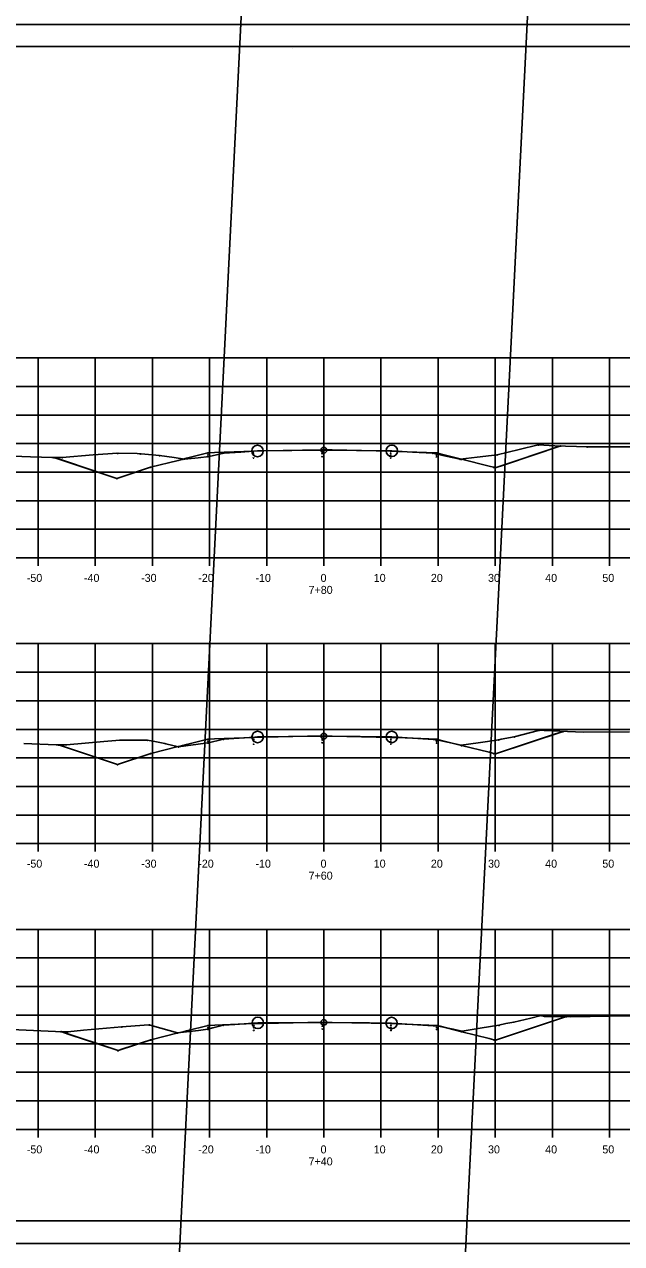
# Model space of a CAD drawing. Extents: x 1300404 to 1323571, y 234004 to 252077.
# Drawn here: x 1315664.9 to 1315769.4, y 242555.1 to 242768.5 of the extents above; entities that cross this region are included whole.
import ezdxf

# ---------------------------------------------------------------- set-up
doc = ezdxf.new("R2010")
doc.units = 0
for name, color, linetype in [('Default', 7, 'Continuous'), ('R_Axis', 7, 'Continuous'), ('R_Axis Annot', 7, 'Continuous'), ('R_Border', 7, 'Continuous'), ('R_Draft', 7, 'Continuous'), ('R_Exist Surface', 7, 'Continuous'), ('R_Fin Surface', 7, 'Continuous'), ('R_Floodway', 7, 'Continuous'), ('R_Grid', 7, 'Continuous'), ('R_No Plot', 7, 'Continuous')]:
    doc.layers.add(name, color=color, linetype=linetype)

msp = doc.modelspace()

# ---------------------------------------------------------------- linework, layer by layer
at = {"layer": 'Default'}
for p, q in [((1315559.28, 242764.58), (1315875.46, 242764.58)), ((1315875.46, 242559.12), (1315559.28, 242559.12))]:
    msp.add_line(p, q, dxfattribs=at)
at = {"layer": 'R_Axis'}
for p, q in [((1315577.28, 242675.12), (1315857.28, 242675.12)), ((1315667.28, 242673.72), (1315667.28, 242675.12)), ((1315677.28, 242673.72), (1315677.28, 242675.12)), ((1315687.28, 242673.72), (1315687.28, 242675.12)), ((1315697.28, 242673.72), (1315697.28, 242675.12)), ((1315707.28, 242673.72), (1315707.28, 242675.12)), ((1315717.28, 242673.72), (1315717.28, 242675.12)), ((1315727.28, 242673.72), (1315727.28, 242675.12)), ((1315737.28, 242673.72), (1315737.28, 242675.12)), ((1315747.28, 242673.72), (1315747.28, 242675.12)), ((1315757.28, 242673.72), (1315757.28, 242675.12)), ((1315767.28, 242673.72), (1315767.28, 242675.12)), ((1315577.28, 242625.12), (1315857.28, 242625.12)), ((1315667.28, 242623.72), (1315667.28, 242625.12)), ((1315677.28, 242623.72), (1315677.28, 242625.12)), ((1315687.28, 242623.72), (1315687.28, 242625.12)), ((1315697.28, 242623.72), (1315697.28, 242625.12)), ((1315707.28, 242623.72), (1315707.28, 242625.12)), ((1315717.28, 242623.72), (1315717.28, 242625.12)), ((1315727.28, 242623.72), (1315727.28, 242625.12)), ((1315737.28, 242623.72), (1315737.28, 242625.12)), ((1315747.28, 242623.72), (1315747.28, 242625.12)), ((1315757.28, 242623.72), (1315757.28, 242625.12)), ((1315767.28, 242623.72), (1315767.28, 242625.12)), ((1315577.28, 242575.12), (1315857.28, 242575.12)), ((1315667.28, 242573.72), (1315667.28, 242575.12)), ((1315677.28, 242573.72), (1315677.28, 242575.12)), ((1315687.28, 242573.72), (1315687.28, 242575.12)), ((1315697.28, 242573.72), (1315697.28, 242575.12)), ((1315707.28, 242573.72), (1315707.28, 242575.12)), ((1315717.28, 242573.72), (1315717.28, 242575.12)), ((1315727.28, 242573.72), (1315727.28, 242575.12)), ((1315737.28, 242573.72), (1315737.28, 242575.12)), ((1315747.28, 242573.72), (1315747.28, 242575.12)), ((1315757.28, 242573.72), (1315757.28, 242575.12)), ((1315767.28, 242573.72), (1315767.28, 242575.12))]:
    msp.add_line(p, q, dxfattribs=at)
at = {"layer": 'R_Border'}
msp.add_line((1315711.8, 242764.32), (1315711.8, 242764.32), dxfattribs=at)
msp.add_line((1315711.8, 242764.32), (1315711.8, 242764.32), dxfattribs=at)
at = {"layer": 'R_Draft'}
for points in [[(1315681.19, 242693.48), (1315681.24, 242693.38), (1315681.14, 242693.38)], [(1315685.16, 242693.4), (1315685.21, 242693.3), (1315685.11, 242693.3)], [(1315696.98, 242693.54), (1315697.03, 242693.44), (1315696.93, 242693.44)], [(1315699.78, 242693.52), (1315699.83, 242693.42), (1315699.73, 242693.42)], [(1315704.98, 242693.86), (1315705.03, 242693.76), (1315704.93, 242693.76)], [(1315704.98, 242693.53), (1315705.03, 242693.43), (1315704.93, 242693.43)], [(1315716.98, 242694.1), (1315717.03, 242694), (1315716.93, 242694)], [(1315716.98, 242693.77), (1315717.03, 242693.67), (1315716.93, 242693.67)], [(1315716.98, 242693.44), (1315717.03, 242693.34), (1315716.93, 242693.34)], [(1315728.98, 242693.86), (1315729.03, 242693.76), (1315728.93, 242693.76)], [(1315728.98, 242693.53), (1315729.03, 242693.43), (1315728.93, 242693.43)], [(1315736.36, 242693.48), (1315736.41, 242693.38), (1315736.31, 242693.38)], [(1315736.98, 242693.54), (1315737.03, 242693.44), (1315736.93, 242693.44)], [(1315754.81, 242694.93), (1315754.86, 242694.83), (1315754.76, 242694.83)], [(1315758.72, 242694.76), (1315758.77, 242694.66), (1315758.67, 242694.66)], [(1315758.72, 242694.76), (1315758.77, 242694.66), (1315758.67, 242694.66)], [(1315763.34, 242694.6), (1315763.39, 242694.5), (1315763.29, 242694.5)], [(1315670.04, 242692.75), (1315670.09, 242692.65), (1315669.99, 242692.65)], [(1315670.04, 242692.75), (1315670.09, 242692.65), (1315669.99, 242692.65)], [(1315671.52, 242692.75), (1315671.57, 242692.65), (1315671.47, 242692.65)], [(1315688.51, 242693.09), (1315688.56, 242692.99), (1315688.46, 242692.99)], [(1315692.61, 242692.45), (1315692.66, 242692.35), (1315692.56, 242692.35)], [(1315692.88, 242692.47), (1315692.93, 242692.37), (1315692.83, 242692.37)], [(1315696.98, 242693.21), (1315697.03, 242693.11), (1315696.93, 242693.11)], [(1315696.98, 242692.88), (1315697.03, 242692.78), (1315696.93, 242692.78)], [(1315697.23, 242692.89), (1315697.28, 242692.79), (1315697.18, 242692.79)], [(1315704.98, 242693.19), (1315705.03, 242693.09), (1315704.93, 242693.09)], [(1315704.98, 242692.69), (1315705.03, 242692.59), (1315704.93, 242692.59)], [(1315716.98, 242692.93), (1315717.03, 242692.83), (1315716.93, 242692.83)], [(1315728.98, 242693.2), (1315729.03, 242693.1), (1315728.93, 242693.1)], [(1315728.98, 242692.69), (1315729.03, 242692.59), (1315728.93, 242692.59)], [(1315736.98, 242693.21), (1315737.03, 242693.11), (1315736.93, 242693.11)], [(1315736.98, 242692.88), (1315737.03, 242692.78), (1315736.93, 242692.78)], [(1315741.13, 242692.42), (1315741.18, 242692.32), (1315741.08, 242692.32)], [(1315741.36, 242692.45), (1315741.41, 242692.35), (1315741.31, 242692.35)], [(1315747.59, 242693.22), (1315747.64, 242693.12), (1315747.54, 242693.12)], [(1315681.08, 242689.07), (1315681.13, 242688.97), (1315681.03, 242688.97)], [(1315686.98, 242691.04), (1315687.03, 242690.94), (1315686.93, 242690.94)], [(1315746.98, 242691.04), (1315747.03, 242690.94), (1315746.93, 242690.94)], [(1315747.27, 242690.95), (1315747.32, 242690.85), (1315747.22, 242690.85)], [(1315755.05, 242645.02), (1315755.1, 242644.92), (1315755, 242644.92)], [(1315759.15, 242644.81), (1315759.2, 242644.71), (1315759.1, 242644.71)], [(1315759.15, 242644.81), (1315759.2, 242644.71), (1315759.1, 242644.71)], [(1315670.85, 242642.46), (1315670.9, 242642.36), (1315670.8, 242642.36)], [(1315670.85, 242642.46), (1315670.9, 242642.36), (1315670.8, 242642.36)], [(1315672.24, 242642.49), (1315672.29, 242642.39), (1315672.19, 242642.39)], [(1315681.58, 242643.3), (1315681.63, 242643.2), (1315681.53, 242643.2)], [(1315686.4, 242643.29), (1315686.45, 242643.19), (1315686.35, 242643.19)], [(1315692.63, 242642.36), (1315692.68, 242642.26), (1315692.58, 242642.26)], [(1315697, 242643.45), (1315697.05, 242643.35), (1315696.95, 242643.35)], [(1315697, 242643.12), (1315697.05, 242643.02), (1315696.95, 242643.02)], [(1315697, 242642.79), (1315697.05, 242642.69), (1315696.95, 242642.69)], [(1315697.11, 242642.8), (1315697.16, 242642.7), (1315697.06, 242642.7)], [(1315699.74, 242643.47), (1315699.79, 242643.37), (1315699.69, 242643.37)], [(1315705, 242643.77), (1315705.05, 242643.67), (1315704.95, 242643.67)], [(1315705, 242643.44), (1315705.05, 242643.34), (1315704.95, 242643.34)], [(1315705, 242643.11), (1315705.05, 242643.01), (1315704.95, 242643.01)], [(1315705, 242642.61), (1315705.05, 242642.51), (1315704.95, 242642.51)], [(1315717, 242644.01), (1315717.05, 242643.91), (1315716.95, 242643.91)], [(1315717, 242643.68), (1315717.05, 242643.58), (1315716.95, 242643.58)], [(1315717, 242643.35), (1315717.05, 242643.25), (1315716.95, 242643.25)], [(1315717, 242642.85), (1315717.05, 242642.75), (1315716.95, 242642.75)], [(1315729, 242643.77), (1315729.05, 242643.67), (1315728.95, 242643.67)], [(1315729, 242643.44), (1315729.05, 242643.34), (1315728.95, 242643.34)], [(1315729, 242643.11), (1315729.05, 242643.01), (1315728.95, 242643.01)], [(1315729, 242642.61), (1315729.05, 242642.51), (1315728.95, 242642.51)], [(1315736.85, 242643.36), (1315736.9, 242643.26), (1315736.8, 242643.26)], [(1315737, 242643.45), (1315737.05, 242643.35), (1315736.95, 242643.35)], [(1315737, 242643.12), (1315737.05, 242643.02), (1315736.95, 242643.02)], [(1315737, 242642.79), (1315737.05, 242642.69), (1315736.95, 242642.69)], [(1315741.32, 242642.4), (1315741.37, 242642.3), (1315741.27, 242642.3)], [(1315741.38, 242642.36), (1315741.43, 242642.26), (1315741.33, 242642.26)], [(1315747.89, 242643.35), (1315747.94, 242643.25), (1315747.84, 242643.25)], [(1315750.61, 242643.88), (1315750.66, 242643.78), (1315750.56, 242643.78)], [(1315687, 242640.95), (1315687.05, 242640.85), (1315686.95, 242640.85)], [(1315691.85, 242642.09), (1315691.9, 242641.99), (1315691.8, 242641.99)], [(1315747, 242640.95), (1315747.05, 242640.85), (1315746.95, 242640.85)], [(1315747.29, 242640.86), (1315747.34, 242640.76), (1315747.24, 242640.76)], [(1315681.18, 242639.01), (1315681.23, 242638.91), (1315681.13, 242638.91)], [(1315681.95, 242593.13), (1315682, 242593.03), (1315681.9, 242593.03)], [(1315686.72, 242593.45), (1315686.77, 242593.35), (1315686.67, 242593.35)], [(1315697.02, 242593.36), (1315697.07, 242593.26), (1315696.97, 242593.26)], [(1315699.7, 242593.41), (1315699.75, 242593.31), (1315699.65, 242593.31)], [(1315705.02, 242593.68), (1315705.07, 242593.58), (1315704.97, 242593.58)], [(1315705.02, 242593.35), (1315705.07, 242593.25), (1315704.97, 242593.25)], [(1315717.02, 242593.92), (1315717.07, 242593.82), (1315716.97, 242593.82)], [(1315717.02, 242593.59), (1315717.07, 242593.49), (1315716.97, 242593.49)], [(1315717.02, 242593.26), (1315717.07, 242593.16), (1315716.97, 242593.16)], [(1315729.02, 242593.68), (1315729.07, 242593.58), (1315728.97, 242593.58)], [(1315729.02, 242593.35), (1315729.07, 242593.25), (1315728.97, 242593.25)], [(1315737.02, 242593.36), (1315737.07, 242593.26), (1315736.97, 242593.26)], [(1315737.33, 242593.25), (1315737.38, 242593.15), (1315737.28, 242593.15)], [(1315747.91, 242593.38), (1315747.96, 242593.28), (1315747.86, 242593.28)], [(1315750.51, 242593.96), (1315750.56, 242593.86), (1315750.46, 242593.86)], [(1315755.28, 242595.11), (1315755.33, 242595.01), (1315755.23, 242595.01)], [(1315759.74, 242594.91), (1315759.79, 242594.81), (1315759.69, 242594.81)], [(1315759.74, 242594.91), (1315759.79, 242594.81), (1315759.69, 242594.81)], [(1315671.26, 242592.29), (1315671.31, 242592.19), (1315671.21, 242592.19)], [(1315671.26, 242592.29), (1315671.31, 242592.19), (1315671.21, 242592.19)], [(1315672.47, 242592.26), (1315672.52, 242592.16), (1315672.42, 242592.16)], [(1315691.69, 242592.07), (1315691.74, 242591.97), (1315691.64, 242591.97)], [(1315692.64, 242592.27), (1315692.69, 242592.17), (1315692.59, 242592.17)], [(1315696.99, 242592.72), (1315697.04, 242592.62), (1315696.94, 242592.62)], [(1315697.02, 242593.03), (1315697.07, 242592.93), (1315696.97, 242592.93)], [(1315697.02, 242592.7), (1315697.07, 242592.6), (1315696.97, 242592.6)], [(1315705.02, 242593.02), (1315705.07, 242592.92), (1315704.97, 242592.92)], [(1315705.02, 242592.52), (1315705.07, 242592.42), (1315704.97, 242592.42)], [(1315717.02, 242592.76), (1315717.07, 242592.66), (1315716.97, 242592.66)], [(1315729.02, 242593.02), (1315729.07, 242592.92), (1315728.97, 242592.92)], [(1315729.02, 242592.52), (1315729.07, 242592.42), (1315728.97, 242592.42)], [(1315737.02, 242593.03), (1315737.07, 242592.93), (1315736.97, 242592.93)], [(1315737.02, 242592.7), (1315737.07, 242592.6), (1315736.97, 242592.6)], [(1315741.4, 242592.27), (1315741.45, 242592.17), (1315741.35, 242592.17)], [(1315741.5, 242592.38), (1315741.55, 242592.28), (1315741.45, 242592.28)], [(1315681.28, 242588.95), (1315681.33, 242588.85), (1315681.23, 242588.85)], [(1315687.02, 242590.86), (1315687.07, 242590.76), (1315686.97, 242590.76)], [(1315747.02, 242590.86), (1315747.07, 242590.76), (1315746.97, 242590.76)], [(1315747.3, 242590.77), (1315747.35, 242590.67), (1315747.25, 242590.67)]]:
    msp.add_lwpolyline(points, close=True, dxfattribs=at)
at = {"layer": 'R_Exist Surface'}
for points in [[(1315658.35, 242693.07), (1315665.95, 242692.82), (1315667.9, 242692.72), (1315669.7, 242692.69), (1315671.52, 242692.7), (1315676.93, 242693.14), (1315681.19, 242693.43), (1315684.6, 242693.38), (1315685.16, 242693.35), (1315685.34, 242693.34), (1315688.51, 242693.04), (1315691.08, 242692.68), (1315692.88, 242692.42), (1315695.28, 242692.65), (1315697.23, 242692.84), (1315698.51, 242693.16), (1315699.78, 242693.47), (1315702.75, 242693.65), (1315705.67, 242693.83), (1315711.7, 242693.9), (1315717.3, 242693.96), (1315723.01, 242693.9), (1315729.18, 242693.85), (1315732.82, 242693.64), (1315736.36, 242693.43), (1315738.61, 242692.93), (1315741.13, 242692.37), (1315744.08, 242692.76), (1315747.59, 242693.17), (1315751.47, 242694.1), (1315754.81, 242694.88), (1315757.71, 242694.72), (1315763.34, 242694.55), (1315772.4, 242694.53)], [(1315664.78, 242642.62), (1315670.46, 242642.39), (1315672.24, 242642.44), (1315678.76, 242643.01), (1315681.58, 242643.25), (1315682.32, 242643.21), (1315686.4, 242643.24), (1315687.98, 242642.96), (1315689.44, 242642.64), (1315689.63, 242642.59), (1315691.85, 242642.04), (1315696.59, 242642.68), (1315697.11, 242642.75), (1315699.51, 242643.36), (1315699.74, 242643.42), (1315705.23, 242643.76), (1315705.7, 242643.79), (1315716.45, 242643.9), (1315717.28, 242643.91), (1315718.15, 242643.9), (1315729.16, 242643.79), (1315736.42, 242643.34), (1315736.85, 242643.31), (1315737.06, 242643.27), (1315741.32, 242642.35), (1315744.26, 242642.78), (1315747.89, 242643.3), (1315748.28, 242643.39), (1315748.32, 242643.39), (1315750.61, 242643.83), (1315754.84, 242644.92), (1315755.05, 242644.97), (1315755.81, 242644.92), (1315762.65, 242644.63), (1315770.79, 242644.69)], [(1315657.46, 242592.81), (1315670.33, 242592.26), (1315671.96, 242592.2), (1315672.47, 242592.21), (1315675.25, 242592.46), (1315681.95, 242593.08), (1315685.84, 242593.35), (1315686.72, 242593.4), (1315687.28, 242593.23), (1315691.69, 242592.02), (1315695.33, 242592.42), (1315696.99, 242592.67), (1315697.83, 242592.88), (1315699.7, 242593.36), (1315701.69, 242593.49), (1315705.74, 242593.75), (1315709.58, 242593.79), (1315717.27, 242593.85), (1315725.28, 242593.77), (1315729.14, 242593.73), (1315731.82, 242593.56), (1315737.33, 242593.2), (1315739.92, 242592.67), (1315741.5, 242592.33), (1315744.61, 242592.83), (1315747.91, 242593.33), (1315749.13, 242593.66), (1315750.51, 242593.91), (1315753.49, 242594.59), (1315755.28, 242595.06), (1315755.87, 242594.85), (1315758.86, 242594.86), (1315760.36, 242594.84), (1315770.81, 242594.98)]]:
    msp.add_lwpolyline(points, dxfattribs=at)
at = {"layer": 'R_Fin Surface'}
for points in [[(1315670.04, 242692.7), (1315671.73, 242692.14), (1315681.08, 242689.02), (1315681.95, 242689.31), (1315686.98, 242690.99), (1315691.78, 242692.19), (1315692.61, 242692.4), (1315693.25, 242692.56), (1315696.98, 242693.49), (1315698.15, 242693.54), (1315704.98, 242693.81), (1315706.73, 242693.85), (1315716.98, 242694.05), (1315718.71, 242694.02), (1315728.98, 242693.81), (1315730.13, 242693.76), (1315736.98, 242693.49), (1315737.61, 242693.33), (1315741.36, 242692.4), (1315746.19, 242691.19), (1315746.98, 242690.99), (1315747.02, 242690.98), (1315747.27, 242690.9), (1315748.88, 242691.43), (1315758.72, 242694.71)], [(1315670.85, 242642.41), (1315672.42, 242641.88), (1315681.18, 242638.96), (1315682.04, 242639.25), (1315687, 242640.9), (1315691.8, 242642.1), (1315692.63, 242642.31), (1315693.27, 242642.47), (1315697, 242643.4), (1315698.17, 242643.45), (1315705, 242643.72), (1315706.74, 242643.76), (1315717, 242643.96), (1315718.73, 242643.93), (1315729, 242643.72), (1315730.15, 242643.68), (1315737, 242643.4), (1315737.63, 242643.25), (1315741.38, 242642.31), (1315746.21, 242641.1), (1315747, 242640.9), (1315747.04, 242640.89), (1315747.29, 242640.81), (1315757.48, 242644.21), (1315759.15, 242644.76)], [(1315671.26, 242592.24), (1315672.75, 242591.75), (1315681.28, 242588.9), (1315682.13, 242589.19), (1315687.02, 242590.81), (1315691.82, 242592.01), (1315692.64, 242592.22), (1315693.28, 242592.38), (1315697.02, 242593.31), (1315698.19, 242593.36), (1315705.02, 242593.63), (1315706.76, 242593.67), (1315717.02, 242593.87), (1315718.75, 242593.84), (1315729.02, 242593.63), (1315730.16, 242593.59), (1315737.02, 242593.31), (1315737.64, 242593.16), (1315741.4, 242592.22), (1315746.22, 242591.01), (1315747.02, 242590.81), (1315747.06, 242590.8), (1315747.3, 242590.72), (1315757.97, 242594.28), (1315759.74, 242594.86)]]:
    msp.add_lwpolyline(points, dxfattribs=at)
at = {"layer": 'R_Floodway'}
for p, q in [((1315724.08, 242194.52), (1315766.53, 243041.85)), ((1315673.23, 242178.64), (1315715.45, 243021.54))]:
    msp.add_line(p, q, dxfattribs=at)
at = {"layer": 'R_Grid'}
for p, q in [((1315577.28, 242710.12), (1315857.28, 242710.12)), ((1315667.28, 242675.12), (1315667.28, 242710.12)), ((1315677.28, 242675.12), (1315677.28, 242710.12)), ((1315687.28, 242675.12), (1315687.28, 242710.12)), ((1315697.28, 242675.12), (1315697.28, 242710.12)), ((1315707.28, 242675.12), (1315707.28, 242710.12)), ((1315717.28, 242675.12), (1315717.28, 242710.12)), ((1315727.28, 242675.12), (1315727.28, 242710.12)), ((1315737.28, 242675.12), (1315737.28, 242710.12)), ((1315747.28, 242675.12), (1315747.28, 242710.12)), ((1315757.28, 242675.12), (1315757.28, 242710.12)), ((1315767.28, 242675.12), (1315767.28, 242710.12)), ((1315577.28, 242705.12), (1315857.28, 242705.12)), ((1315577.28, 242700.12), (1315857.28, 242700.12)), ((1315577.28, 242695.12), (1315857.28, 242695.12)), ((1315577.28, 242690.12), (1315857.28, 242690.12)), ((1315577.28, 242685.12), (1315857.28, 242685.12)), ((1315577.28, 242680.12), (1315857.28, 242680.12)), ((1315577.28, 242675.12), (1315857.28, 242675.12)), ((1315577.28, 242660.12), (1315857.28, 242660.12)), ((1315667.28, 242625.12), (1315667.28, 242660.12)), ((1315677.28, 242625.12), (1315677.28, 242660.12)), ((1315687.28, 242625.12), (1315687.28, 242660.12)), ((1315697.28, 242625.12), (1315697.28, 242660.12)), ((1315707.28, 242625.12), (1315707.28, 242660.12)), ((1315717.28, 242625.12), (1315717.28, 242660.12)), ((1315727.28, 242625.12), (1315727.28, 242660.12)), ((1315737.28, 242625.12), (1315737.28, 242660.12)), ((1315747.28, 242625.12), (1315747.28, 242660.12)), ((1315757.28, 242625.12), (1315757.28, 242660.12)), ((1315767.28, 242625.12), (1315767.28, 242660.12)), ((1315577.28, 242655.12), (1315857.28, 242655.12)), ((1315577.28, 242650.12), (1315857.28, 242650.12)), ((1315577.28, 242645.12), (1315857.28, 242645.12)), ((1315577.28, 242640.12), (1315857.28, 242640.12)), ((1315577.28, 242635.12), (1315857.28, 242635.12)), ((1315577.28, 242630.12), (1315857.28, 242630.12)), ((1315577.28, 242625.12), (1315857.28, 242625.12)), ((1315577.28, 242610.12), (1315857.28, 242610.12)), ((1315667.28, 242575.12), (1315667.28, 242610.12)), ((1315677.28, 242575.12), (1315677.28, 242610.12)), ((1315687.28, 242575.12), (1315687.28, 242610.12)), ((1315697.28, 242575.12), (1315697.28, 242610.12)), ((1315707.28, 242575.12), (1315707.28, 242610.12)), ((1315717.28, 242575.12), (1315717.28, 242610.12)), ((1315727.28, 242575.12), (1315727.28, 242610.12)), ((1315737.28, 242575.12), (1315737.28, 242610.12)), ((1315747.28, 242575.12), (1315747.28, 242610.12)), ((1315757.28, 242575.12), (1315757.28, 242610.12)), ((1315767.28, 242575.12), (1315767.28, 242610.12)), ((1315577.28, 242605.12), (1315857.28, 242605.12)), ((1315577.28, 242600.12), (1315857.28, 242600.12)), ((1315577.28, 242595.12), (1315857.28, 242595.12)), ((1315577.28, 242590.12), (1315857.28, 242590.12)), ((1315577.28, 242585.12), (1315857.28, 242585.12)), ((1315577.28, 242580.12), (1315857.28, 242580.12)), ((1315577.28, 242575.12), (1315857.28, 242575.12))]:
    msp.add_line(p, q, dxfattribs=at)
at = {"layer": 'R_No Plot'}
for p, q in [((1315546.87, 242768.47), (1315880.21, 242768.47)), ((1315546.87, 242555.14), (1315880.21, 242555.14))]:
    msp.add_line(p, q, dxfattribs=at)
for points in [[(1315546.87, 242768.47), (1315880.21, 242768.47), (1315880.21, 242555.14), (1315546.87, 242555.14)], [(1315793.2, 242764.58), (1315793.2, 242754.7), (1315828.93, 242754.7), (1315828.93, 242751.78), (1315852.13, 242751.78), (1315852.13, 242729.66), (1315875.46, 242729.66), (1315875.46, 242559.12), (1315559.28, 242559.12), (1315559.28, 242764.58)]]:
    msp.add_lwpolyline(points, close=True, dxfattribs=at)
for points in [[(1315746.98, 242690.99), (1315747.27, 242690.9), (1315758.72, 242694.71)], [(1315746.98, 242690.99), (1315747.27, 242690.9), (1315758.72, 242694.71)], [(1315746.98, 242690.99), (1315747.27, 242690.9), (1315758.72, 242694.71)], [(1315746.98, 242690.99), (1315747.27, 242690.9), (1315758.72, 242694.71)], [(1315681.08, 242689.02), (1315670.04, 242692.7)], [(1315686.98, 242690.99), (1315681.08, 242689.02), (1315670.04, 242692.7)], [(1315686.98, 242690.99), (1315681.08, 242689.02), (1315670.04, 242692.7)], [(1315686.98, 242690.99), (1315681.08, 242689.02), (1315670.04, 242692.7)], [(1315686.98, 242690.99), (1315681.08, 242689.02), (1315670.04, 242692.7)], [(1315686.98, 242690.99), (1315681.08, 242689.02), (1315670.04, 242692.7)], [(1315747, 242640.9), (1315747.29, 242640.81), (1315759.15, 242644.76)], [(1315747, 242640.9), (1315747.29, 242640.81), (1315759.15, 242644.76)], [(1315747, 242640.9), (1315747.29, 242640.81), (1315759.15, 242644.76)], [(1315747, 242640.9), (1315747.29, 242640.81), (1315759.15, 242644.76)], [(1315681.18, 242638.96), (1315670.85, 242642.41)], [(1315687, 242640.9), (1315681.18, 242638.96), (1315670.85, 242642.41)], [(1315687, 242640.9), (1315681.18, 242638.96), (1315670.85, 242642.41)], [(1315687, 242640.9), (1315681.18, 242638.96), (1315670.85, 242642.41)], [(1315687, 242640.9), (1315681.18, 242638.96), (1315670.85, 242642.41)], [(1315687, 242640.9), (1315681.18, 242638.96), (1315670.85, 242642.41)], [(1315747.02, 242590.81), (1315747.3, 242590.72), (1315759.74, 242594.86)], [(1315747.02, 242590.81), (1315747.3, 242590.72), (1315759.74, 242594.86)], [(1315747.02, 242590.81), (1315747.3, 242590.72), (1315759.74, 242594.86)], [(1315747.02, 242590.81), (1315747.3, 242590.72), (1315759.74, 242594.86)], [(1315681.28, 242588.9), (1315671.26, 242592.24)], [(1315687.02, 242590.81), (1315681.28, 242588.9), (1315671.26, 242592.24)], [(1315687.02, 242590.81), (1315681.28, 242588.9), (1315671.26, 242592.24)], [(1315687.02, 242590.81), (1315681.28, 242588.9), (1315671.26, 242592.24)], [(1315687.02, 242590.81), (1315681.28, 242588.9), (1315671.26, 242592.24)], [(1315687.02, 242590.81), (1315681.28, 242588.9), (1315671.26, 242592.24)]]:
    msp.add_lwpolyline(points, dxfattribs=at)
for centre, radius in [((1315705.67, 242693.83), 1), ((1315717.3, 242693.96), 0.5), ((1315729.18, 242693.85), 1), ((1315705.7, 242643.79), 1), ((1315717.28, 242643.91), 0.5), ((1315729.16, 242643.79), 1), ((1315705.74, 242593.75), 1), ((1315717.27, 242593.85), 0.5), ((1315729.14, 242593.73), 1)]:
    msp.add_circle(centre, radius, dxfattribs=at)

# ---------------------------------------------------------------- texts
at = {"layer": 'R_Axis Annot'}
for s, p in [('-50', (1315665.31, 242670.92)), ('-40', (1315675.31, 242670.92)), ('-30', (1315685.31, 242670.92)), ('-20', (1315695.31, 242670.92)), ('-10', (1315705.31, 242670.92)), ('0', (1315716.71, 242670.92)), ('10', (1315726.01, 242670.92)), ('20', (1315736.01, 242670.92)), ('30', (1315746.01, 242670.92)), ('40', (1315756.01, 242670.92)), ('50', (1315766.01, 242670.92)), ('7+80', (1315714.61, 242668.82)), ('-50', (1315665.31, 242620.92)), ('-40', (1315675.31, 242620.92)), ('-30', (1315685.31, 242620.92)), ('-20', (1315695.31, 242620.92)), ('-10', (1315705.31, 242620.92)), ('0', (1315716.71, 242620.92)), ('10', (1315726.01, 242620.92)), ('20', (1315736.01, 242620.92)), ('30', (1315746.01, 242620.92)), ('40', (1315756.01, 242620.92)), ('50', (1315766.01, 242620.92)), ('7+60', (1315714.61, 242618.82)), ('-50', (1315665.31, 242570.92)), ('-40', (1315675.31, 242570.92)), ('-30', (1315685.31, 242570.92)), ('-20', (1315695.31, 242570.92)), ('-10', (1315705.31, 242570.92)), ('0', (1315716.71, 242570.92)), ('10', (1315726.01, 242570.92)), ('20', (1315736.01, 242570.92)), ('30', (1315746.01, 242570.92)), ('40', (1315756.01, 242570.92)), ('50', (1315766.01, 242570.92)), ('7+40', (1315714.61, 242568.82))]:
    msp.add_text(s, height=1.4, dxfattribs=at).set_placement(p)

doc.saveas('drawing.dxf')
